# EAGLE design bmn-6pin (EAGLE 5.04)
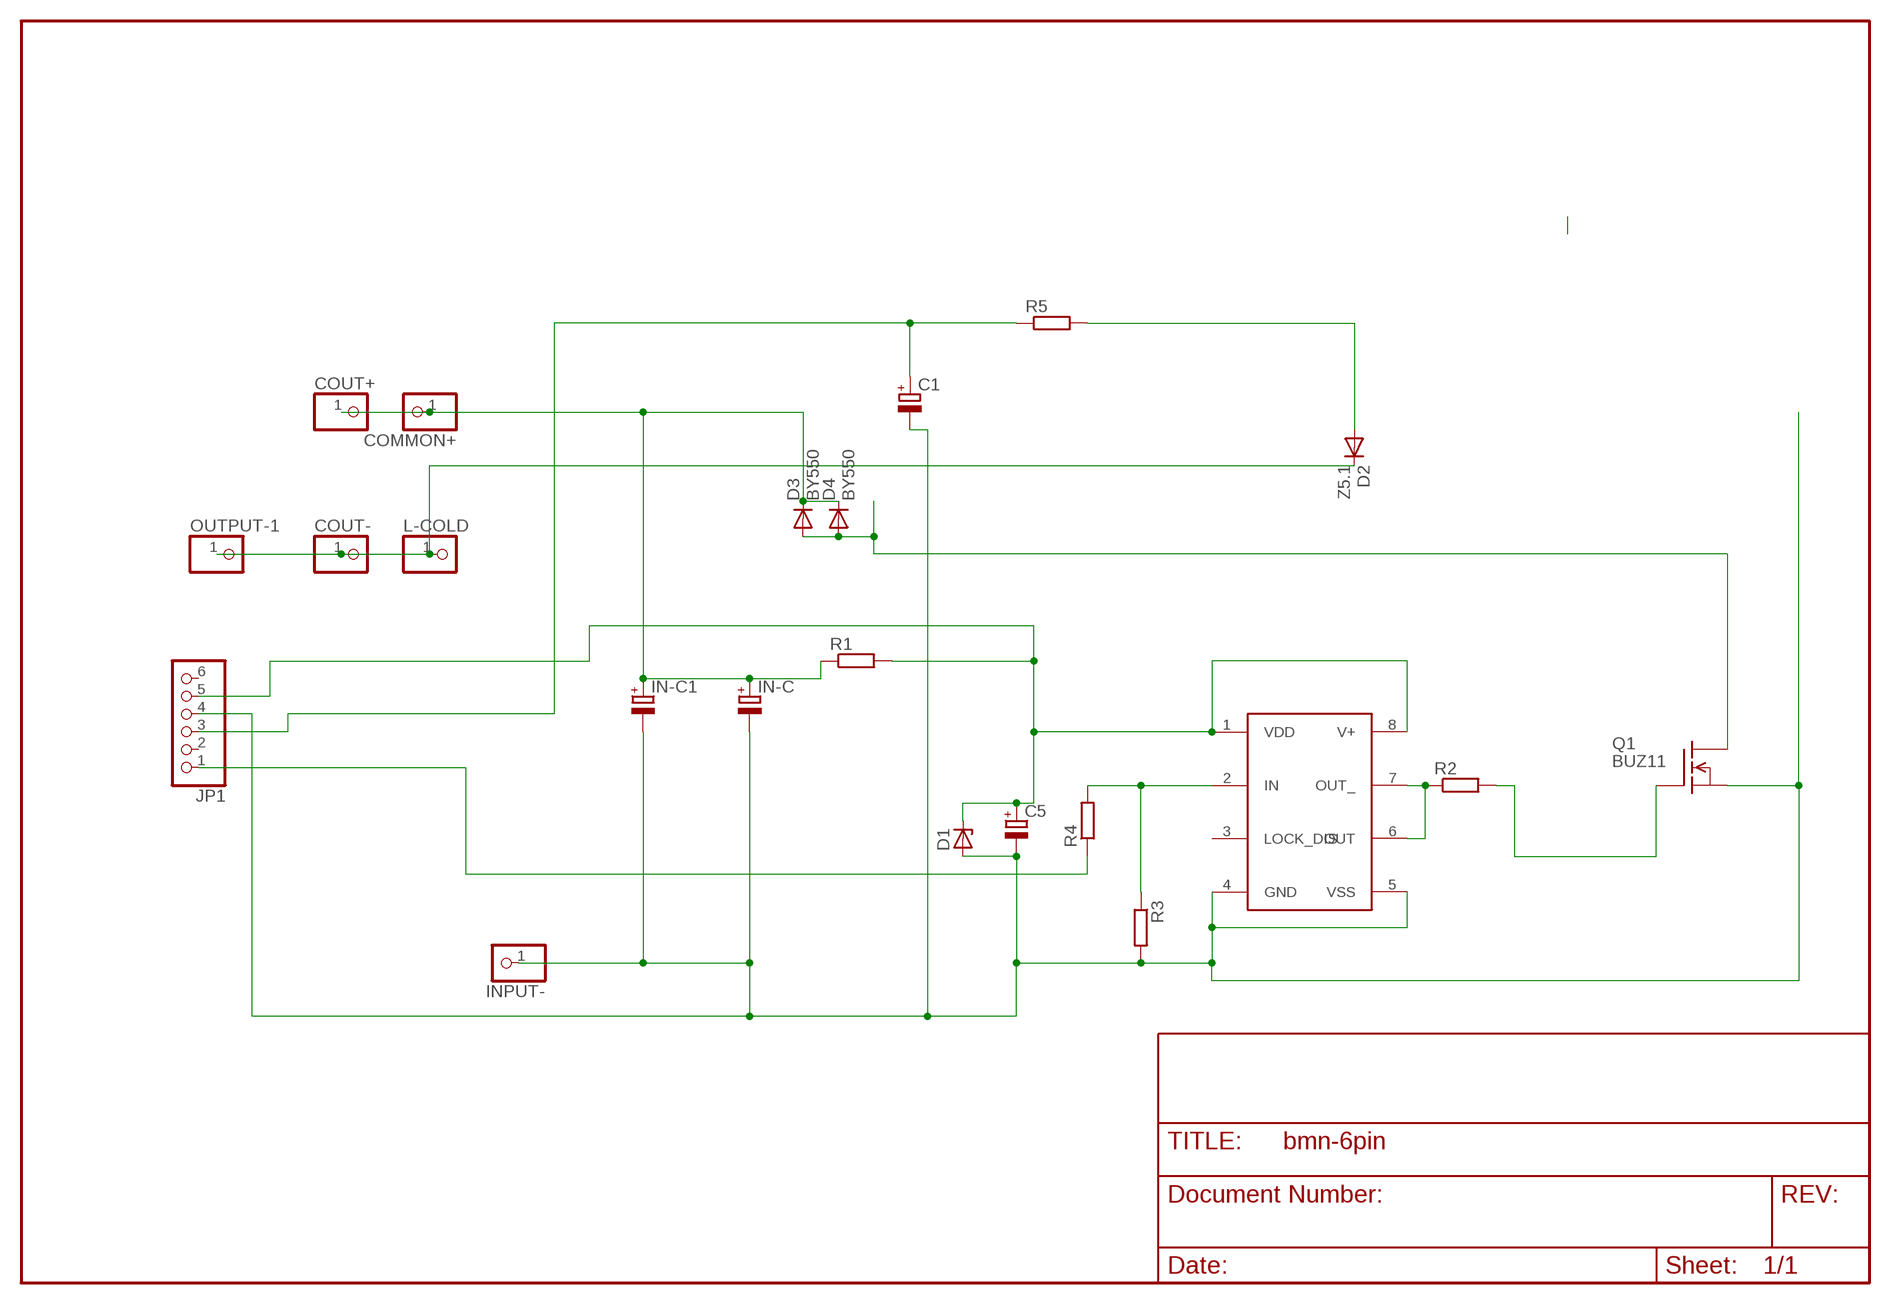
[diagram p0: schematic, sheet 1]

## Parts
C1  CPOL-EUE5-6  [E5-6]
C5  CPOL-EUE5-5  [E5-5]
COMMON+  PINHD-1X1  [1X01]
COUT+  PINHD-1X1  [1X01]
COUT-  PINHD-1X1  [1X01]
D1  ZENER-DIODEZD-5  [ZDIO-5]
D2  Z5.1  DIODE-DO35-10  [DO35-10]
D3  BY550  [DO27-15]
D4  BY550  [DO27-15]
IC1  TC4432X  [SO-08]
IN-C  CPOL-EUE5-8.5  [E5-8,5]
IN-C1  CPOL-EUE2.5-5  [E2,5-5]
INPUT-  PINHD-1X1  [1X01]
JP1  PINHD-1X6  [1X06]
L-COLD  PINHD-1X1  [1X01]
OUTPUT-1  PINHD-1X1  [1X01]
Q1  BUZ11  [TO220]
R1  R-EU_0204/7  [0204/7]
R2  R-EU_R1206  [R1206]
R3  R-EU_R1206  [R1206]
R4  R-EU_R1206  [R1206]
R5  R-EU_R1206  [R1206]

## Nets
COM+: COMMON+.1 COUT+.1 D3.C D4.C IN-C1.+ IN-C.+ R1.1
GND: C1.- C5.- D1.A IC1.4(GND) IC1.5(VSS) IN-C1.- IN-C.- INPUT-.1 JP1.4 Q1.3(S) R3.2
HOTSPOT: D3.A D4.A Q1.2(D)
N$1: IC1.2(IN) R3.1 R4.2
N$2: C1.+ JP1.3 R5.1
N$3: IC1.6(OUT) IC1.7(OUT_) R2.1
N$5: D2.A R5.2
N$6: Q1.1(G) R2.2
N$10: COUT-.1 D2.C L-COLD.1 OUTPUT-1.1
N$11: JP1.1 R4.1
VDD: C5.+ D1.C IC1.1(VDD) IC1.8(V+) JP1.5 R1.2
Unconnected: IC1.3(LOCK_DIS) JP1.2 JP1.6

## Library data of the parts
C1 C5 IN-C IN-C1 = rcl(2):CPOL-EU: POLARIZED CAPACITOR, European symbol
COMMON+ COUT+ COUT- INPUT- L-COLD OUTPUT-1 = pinhead:PINHD-1X1: PIN HEADER
D1 = diode-1:ZENER-DIODE: Z-Diode
D2 = diode:DIODE-: DIODE
D3 D4 = diode-1:BY550: DIODE
IC1 = microchip:TC4432
JP1 = pinhead:PINHD-1X6: PIN HEADER
Q1 = transistor-fet:BUZ11: N-Channel Enhancement MOSFET 50V; 30A; 0,040Ohm
R1-R5 = rcl-2:R-EU_: RESISTOR, European symbol

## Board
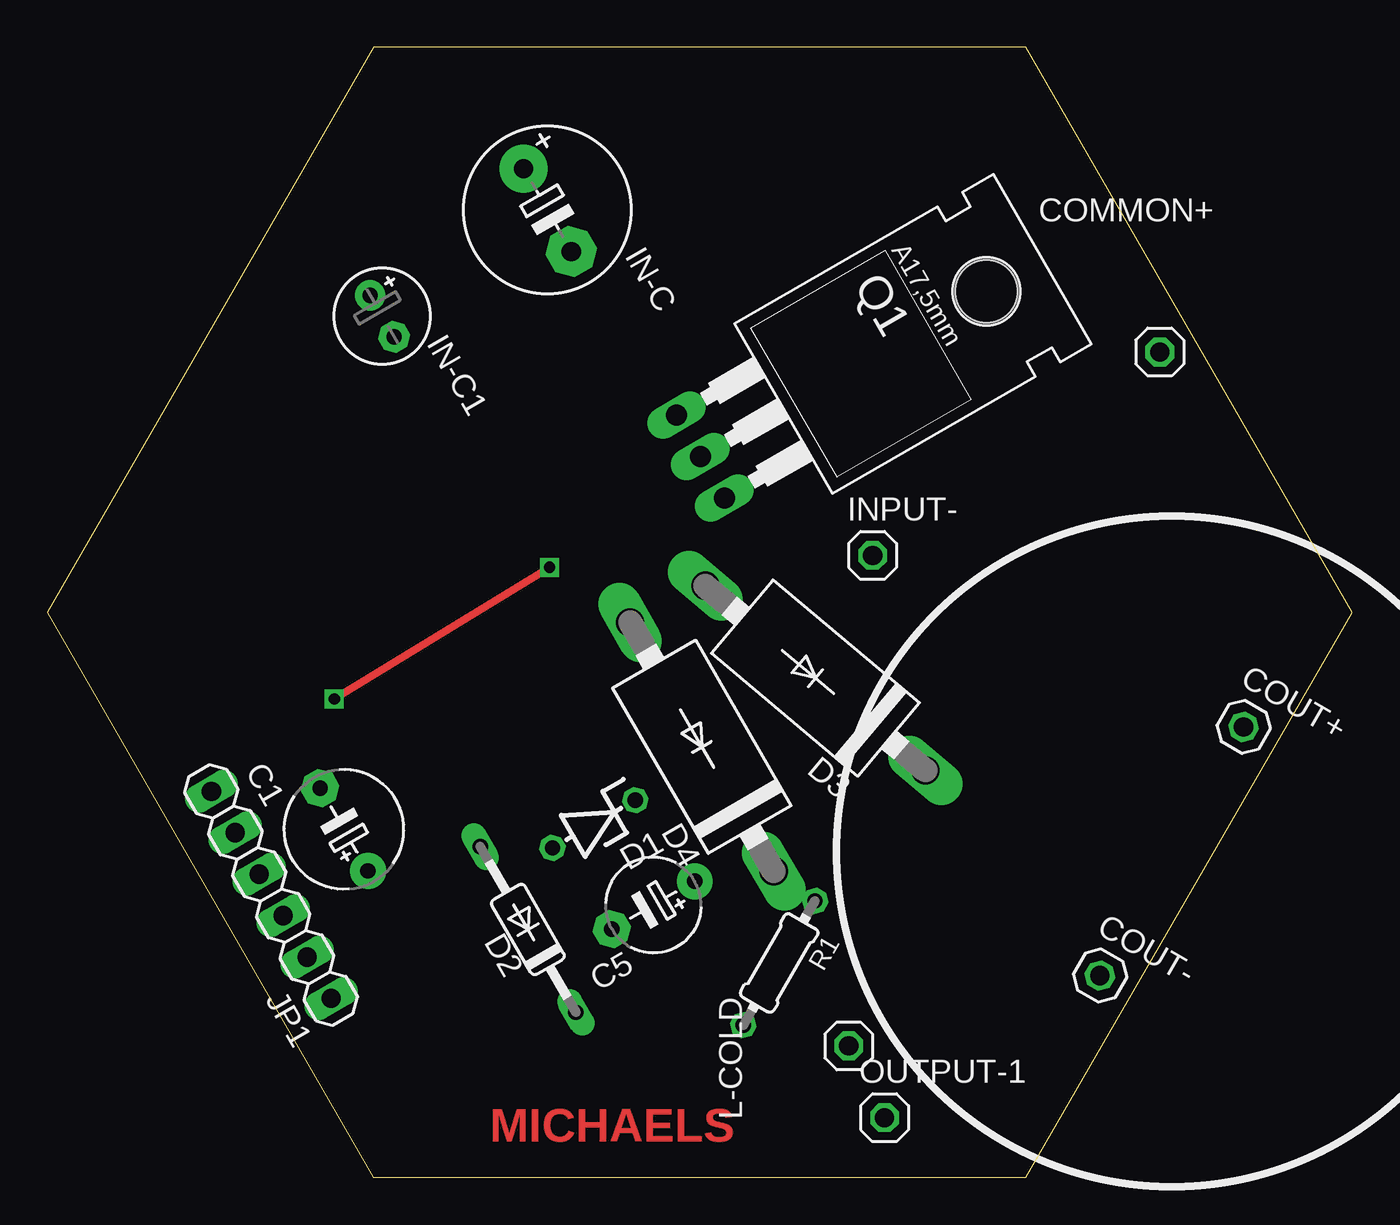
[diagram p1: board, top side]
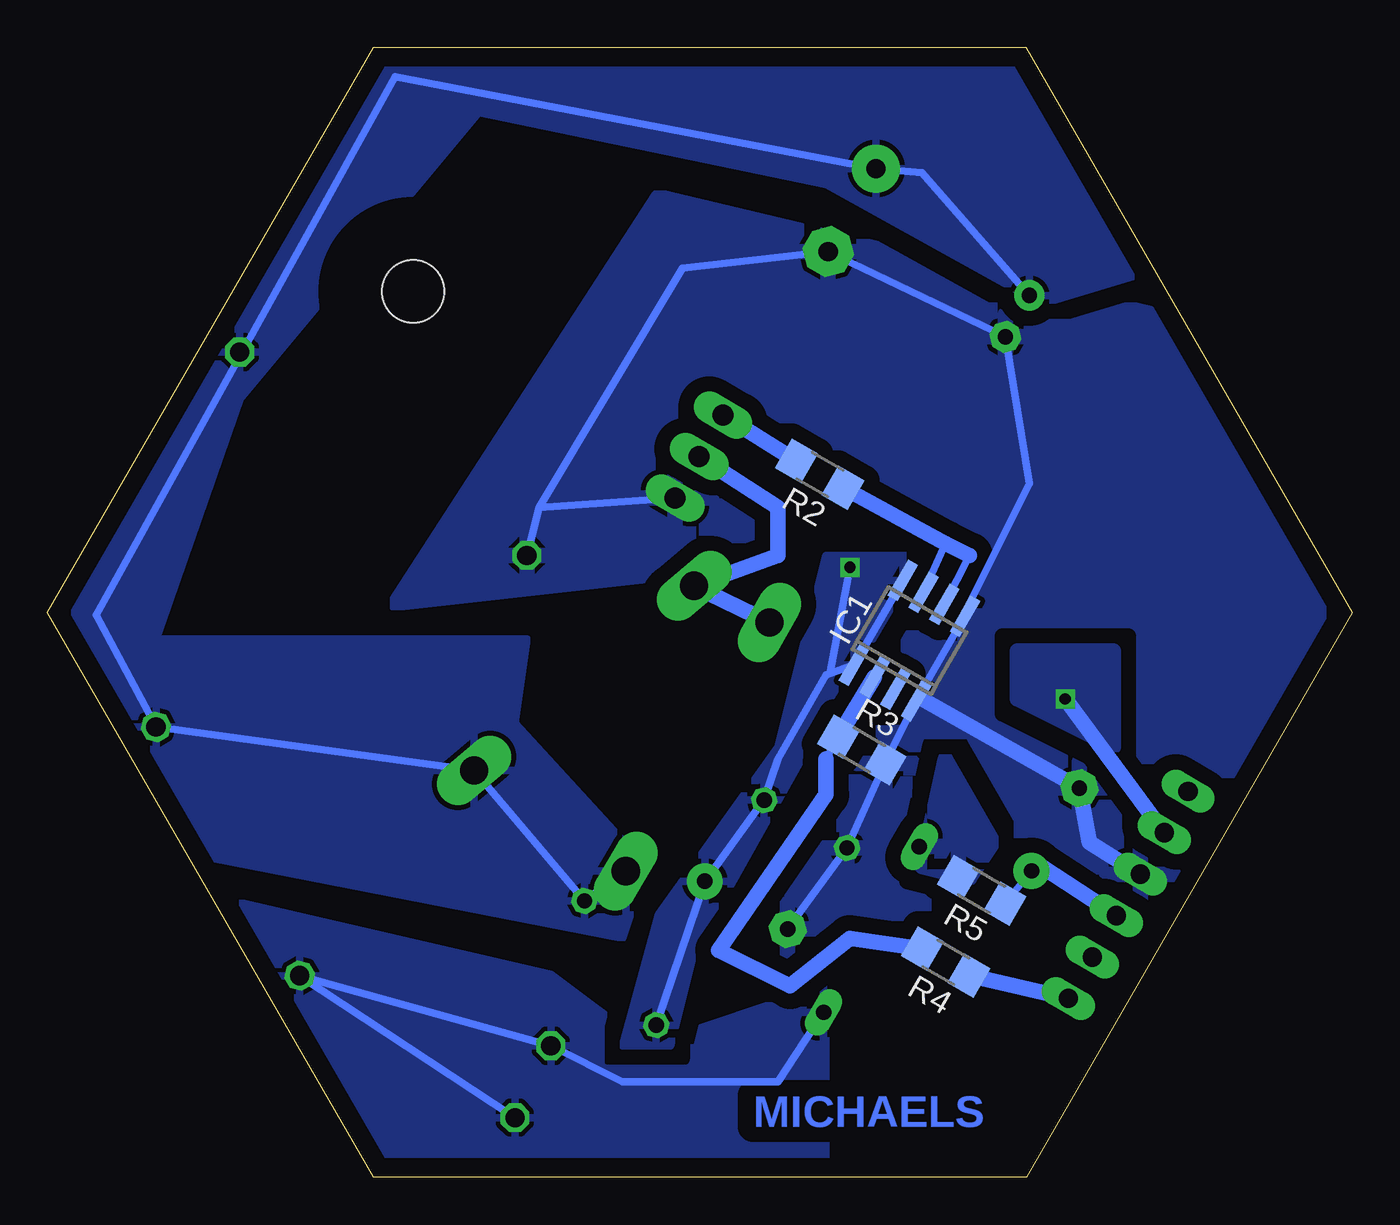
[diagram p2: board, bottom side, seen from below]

Size 69.28 x 60 mm. Coordinates in mm from the lower left corner, seen from the top.
Outline: 17.31,0 51.96,0 69.28,30 51.96,60 17.32,60 0,30 17.31,0
Copper layers (1*16): Top 0.035mm / dielectric 1.5mm / Bottom 0.035mm
Design rules "default": minimum track width 10mil, minimum drill 24mil, track to track 8mil, track to pad 8mil, pad to pad 8mil, via to via 8mil, smd to smd 8mil, copper to edge 40mil, drill to drill 8mil, minimum pad ring 10mil, minimum via ring 8mil, stop-mask expansion 4mil, vias tented up to drill 0mil, thermal gap 10mil

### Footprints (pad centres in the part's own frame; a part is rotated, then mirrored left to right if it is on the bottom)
E5-6 = drill 0.813 pad 1.905 round: + -2.54,0 | drill 0.813 pad 1.905 octagon: - 2.54,0
E5-5 = drill 0.813 pad 1.905 round: + -2.54,0 | drill 0.813 pad 1.905 octagon: - 2.54,0
1X01 = drill 1.016 octagon: 1 0,0
ZDIO-5 = drill 0.813 octagon: A 2.54,0; C -2.54,0
DO35-10 = drill 0.813 long: A 5.08,0; C -5.08,0
DO27-15 = drill 1.499 long: A 7.62,0; C -7.62,0
SO-08 = smd 0.6 x 2.2: 1 -1.905,-2.6; 2 -0.635,-2.6; 3 0.635,-2.6; 4 1.905,-2.6; 5 1.905,2.6; 6 0.635,2.6; 7 -0.635,2.6; 8 -1.905,2.6
E5-8,5 = drill 1.016 pad 2.54 round: + -2.54,0 | drill 1.016 pad 2.54 octagon: - 2.54,0
E2,5-5 = drill 0.813 pad 1.6 round: + -1.27,0 | drill 0.813 pad 1.6 octagon: - 1.27,0
1X06 = drill 1.016 long: 1 -6.35,0; 2 -3.81,0; 3 -1.27,0; 4 1.27,0; 5 3.81,0; 6 6.35,0
TO220 = drill 1.118 long: 1 -2.54,-6.35; 2 0,-6.35; 3 2.54,-6.35 | hole 3.302: 0,11.176
0204/7 = drill 0.813 octagon: 1 -3.81,0; 2 3.81,0
R1206 = smd 1.6 x 1.803: 1 -1.422,0; 2 1.422,0

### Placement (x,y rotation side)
C1  15.76,18.47 120 top
C5  32.17,14.45 210 top
COMMON+  59.05,43.81 0 top
COUT+  63.5,23.91 330 top
COUT-  55.88,10.72 330 top
D1  29.02,18.77 210 top
D2  25.53,13.16 120 top
D3  40.78,26.51 140 top
D4  34.75,22.86 120 top
IC1  23.51,28.49 330 bottom
IN-C  26.55,51.35 300 top
IN-C1  17.78,45.72 300 top
INPUT-  43.81,33.02 0 top
JP1  11.89,15 120 top
L-COLD  42.55,6.99 0 top
OUTPUT-1  44.45,3.17 0 top
Q1  40.18,41.45 300 top
R1  38.85,11.38 240 top
R2  28.27,37.33 150 bottom
R3  26.04,22.69 330 bottom
R4  21.59,11.43 150 bottom
R5  19.68,15.24 150 bottom

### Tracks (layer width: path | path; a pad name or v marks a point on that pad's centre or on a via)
COM+
  Bottom 0.406: IN-C1.+ 22.86,53.34 IN-C.+ 50.8,58.42 66.67,29.84 COUT+.1 D3.C R1.1 D4.C
  pour Bottom (isolate 0.813): 16.51,46.35 10.16,48.26 17.14,59.69 51.44,59.69 69.22,29.21 61.59,17.14 38.73,12.7 37.47,16.51 44.45,24.13 43.81,28.57 63.5,28.57 59.05,41.27 46.35,56.52 27.94,52.7
GND
  Bottom 0.406: C5.- D1.A R3.2 IC1.4 | 22.86,25.4 IC1.4 | IC1.4 IC1.5 20.32,30.48 17.14,36.83 IN-C1.- IN-C.- 35.56,48.26 43.18,35.56 | 43.18,35.56 Q1.3 | 43.18,35.56 INPUT-.1
  Bottom 0.813: JP1.4 13.97,17.78 C1.- 22.86,25.4
  pour Bottom (isolate 0.813, rank 6): 50.8,30.48 36.83,52.07 10.16,45.72 0,30.48 10.16,15.24 30.48,10.16 27.94,33.02
HOTSPOT
  Bottom 0.813: D4.A D3.A 30.48,33.02 30.48,35.56 Q1.2
N$1
  Bottom 0.406: 27.94,22.23 R3.1
  Bottom 0.813: R4.2 26.67,12.7 29.84,10.16 33.66,12.06 27.94,20.32 27.94,22.23 | R3.1 IC1.2
N$2
  Bottom 0.406: 16.51,16.51 C1.+ R5.1
  Bottom 0.813: JP1.3 16.51,16.51
N$3
  Bottom 0.406: 21.59,33.66 IC1.7 | IC1.6 20.32,33.02
  Bottom 0.813: R2.1 21.59,33.66 20.32,33.02
N$5
  pour Bottom (isolate 0.406, rank 3): 21.59,22.23 22.86,16.51 20.32,15.88 19.05,17.78
N$6
  Bottom 0.813: R2.2 Q1.1
N$10
  Bottom 0.406: D2.C 30.48,5.08 38.73,5.08 L-COLD.1 COUT-.1 OUTPUT-1.1
  pour Bottom (isolate 0.813, rank 2): 27.94,10.16 27.94,0 52.7,1.27 58.42,12.06 59.05,14.61 42.55,10.79 37.47,6.99
N$11
  Bottom 0.813: JP1.1 R4.1
VDD  (via drill 0.6)
  Top 0.406: v15.24,25.4 v26.67,32.38
  Bottom 0.406: IC1.8 IC1.1 27.74,26.74 | 27.74,26.74 27.94,26.67 30.48,22.23 D1.C C5.+ R1.2 | v26.67,32.38 27.74,26.74
  Bottom 0.813: JP1.5 v15.24,25.4
  pour Bottom (isolate 0.813): 22.86,33.02 27.94,33.02 30.48,22.86 36.83,13.97 38.73,6.99 36.2,6.99 34.92,12.06 29.21,22.23
  pour Bottom (isolate 0.813): 12.7,22.86 12.7,27.94 17.78,27.94 17.78,25.4

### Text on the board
Top: MICHAELS
Bottom: MICHAELS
